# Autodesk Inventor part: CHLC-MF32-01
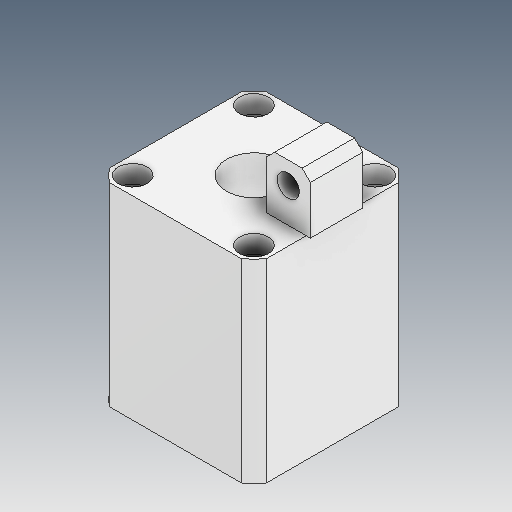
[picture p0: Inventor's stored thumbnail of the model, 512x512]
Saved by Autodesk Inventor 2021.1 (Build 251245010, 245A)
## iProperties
Created: 2021-05
Part Number: CHLC-MF32-01
Material: Ogólny
Document SubType Name: Modeling
Designer: user
Density: 1 g/cm^3
Appearance: Domyślna
Author: user
Revision Number: ÈÎºÎ
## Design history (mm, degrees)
feature "ÊäÈë1"
node "Bryła1"
